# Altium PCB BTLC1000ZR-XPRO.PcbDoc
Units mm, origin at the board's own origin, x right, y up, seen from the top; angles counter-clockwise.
Board outline 66.5 x 30 mm, 4 copper layers (Top Layer LF-signals, GND, Mid-Layer 1, Bottom Layer LF-signals), stack 1.807 mm thick; 79 components, 62 nets, 283 pads, 205 vias.
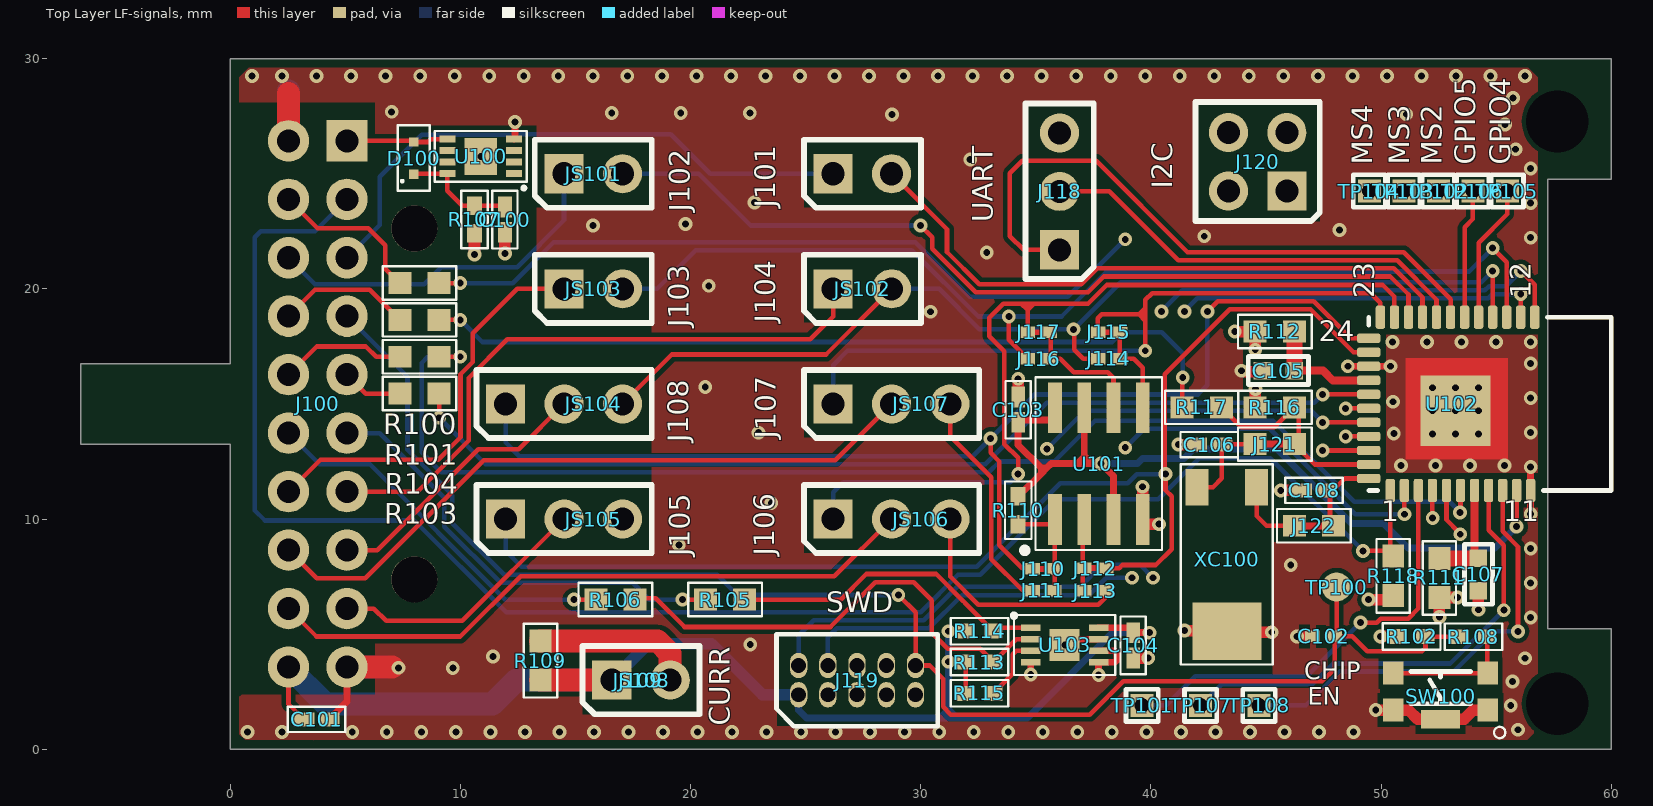
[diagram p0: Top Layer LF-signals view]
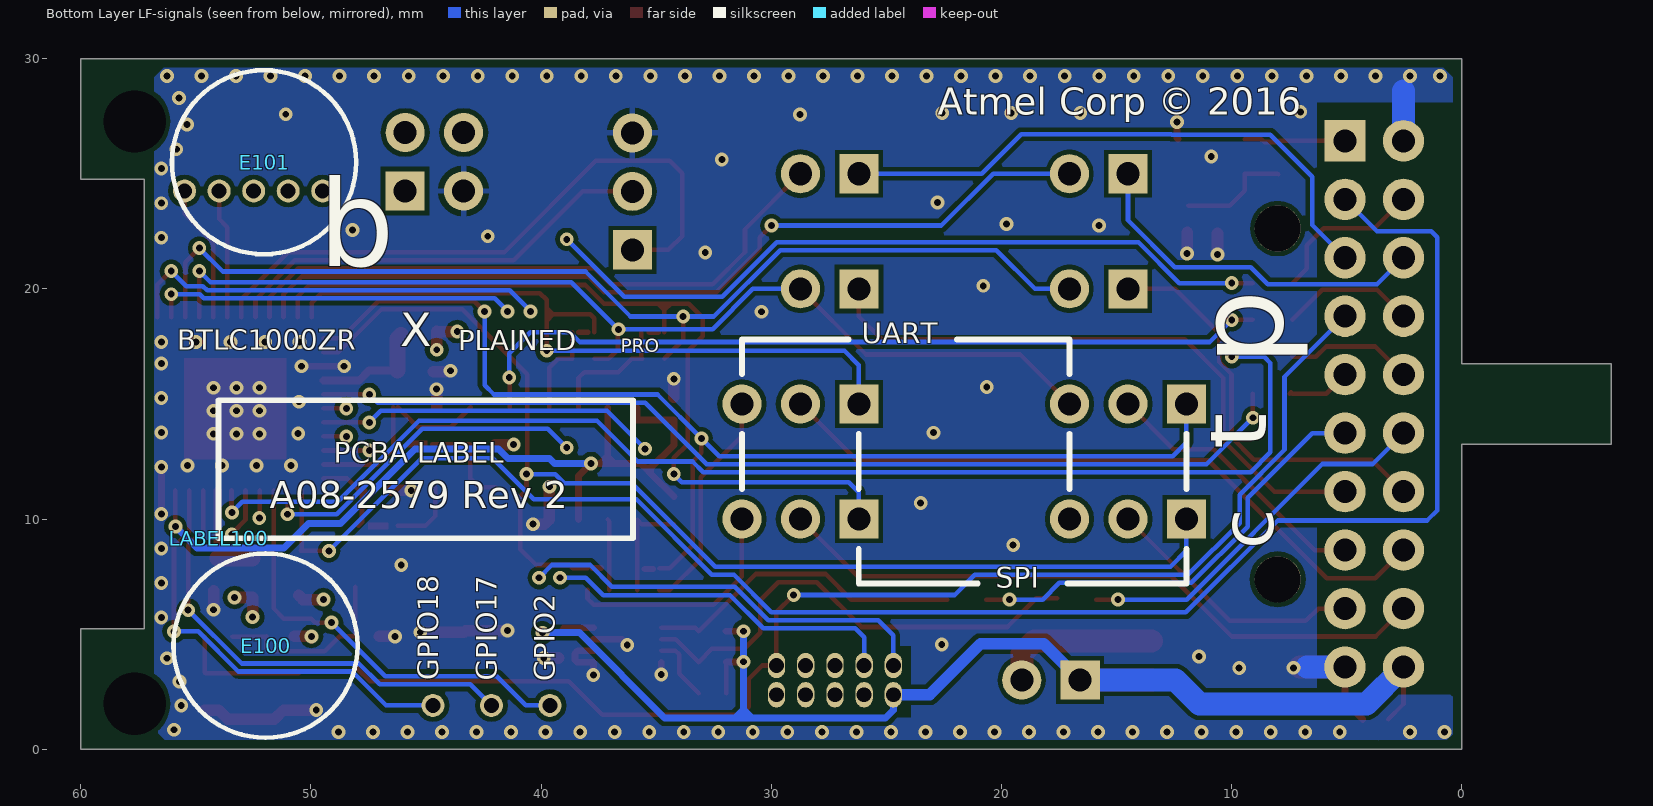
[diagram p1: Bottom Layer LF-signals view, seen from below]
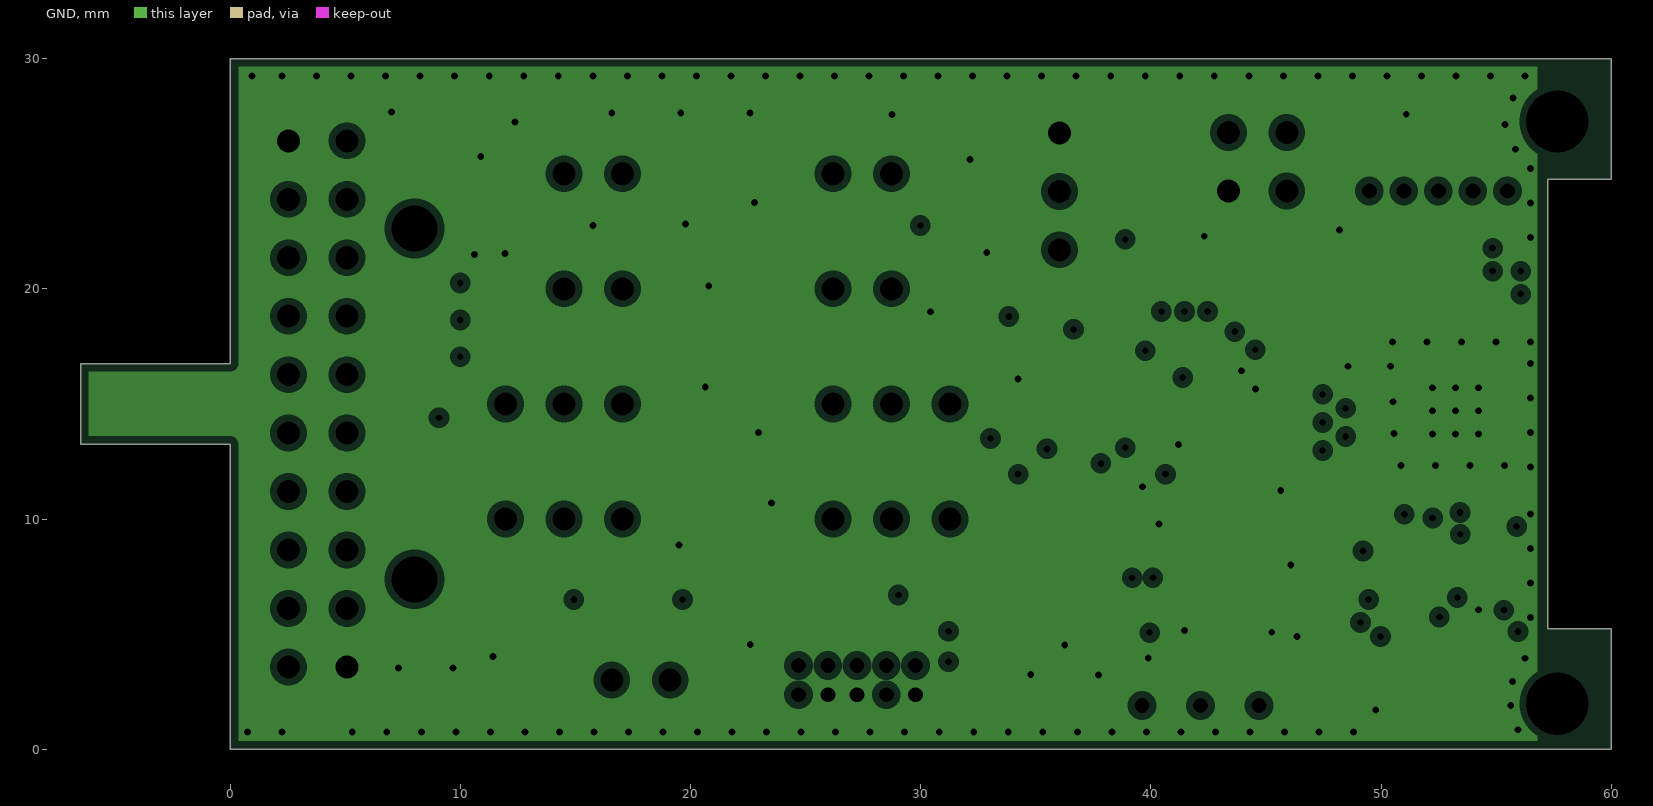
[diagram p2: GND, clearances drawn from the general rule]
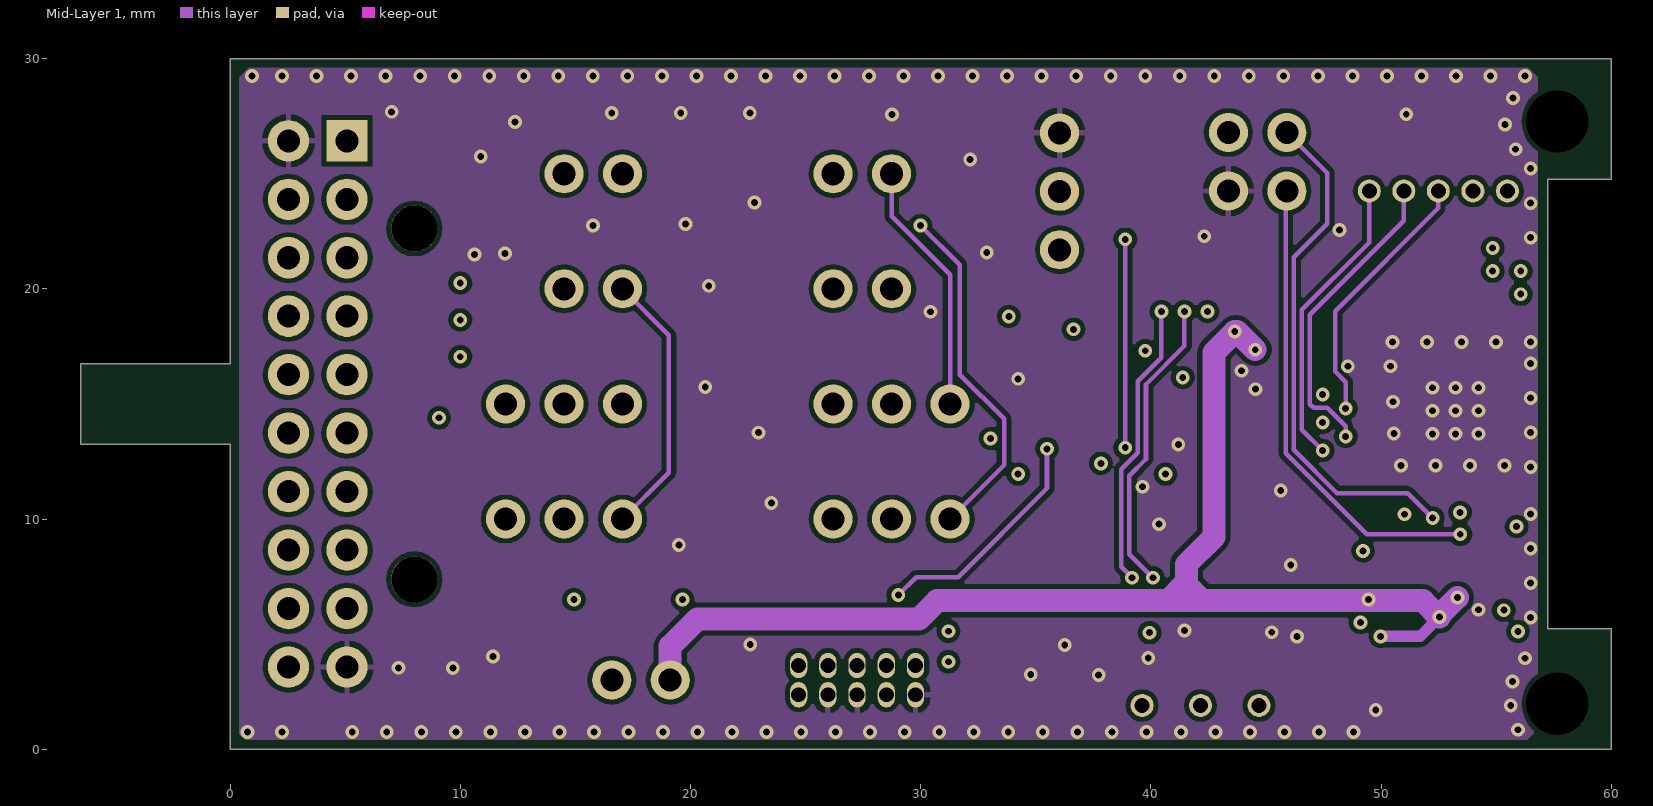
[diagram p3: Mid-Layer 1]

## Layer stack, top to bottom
Top Solder: solder mask 0.0102, Solder Resist, Dk 3.5
Top Layer LF-signals: signal copper 0.049
Dielectric1: core 0.118, FR-4, Dk 4.8
GND: plane copper 0.0356
Dielectric6: prepreg 1.2, FR-4, Dk 4.8
Mid-Layer 1: signal copper 0.0356
Dielectric2: core 0.32, FR-4, Dk 4.8
Bottom Layer LF-signals: signal copper 0.049
Bottom Solder: solder mask 0.0102, Solder Resist, Dk 3.5

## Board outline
-6.5,13.25 -6.5,16.75 0,16.75 0,30 60,30 60,24.769 57.229,24.769 57.229,5.24 60,5.24 60,0 0,0 0,13.25

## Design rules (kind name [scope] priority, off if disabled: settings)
AcuteAngle [All] p1: minimum=8.50000000000000E+0001 checktracksonly=FALSE
AssemblyTestPointUsage [All] p1: allowmultiple=TRUE
AssemblyTestpoint [(IsPad And OnMultiLayer)] p1: testpointundercomponent=TRUE minsize=0.55 maxsize=2 preferedsize=0.8 minholesize=0 maxholesize=1 preferedholesize=0.25 testpointgrid=0.025 usegrid=FALSE gridtolerance=0 allowsidebottom=TRUE minspacing=1.27 compbodyclearance=0.127
Clearance Clearance_POLY [InPolygon] p1: gap=0.203
Clearance [All] p2: gap=0.15
ComponentClearance [All] p1: gap=0.1 collisioncheckmode=3 verticalgap=0.1 showdistances=FALSE
DiffPairsRouting [All] p1: maxlimit=0.3 minlimit=0.15 mostfreqgap=0.2 toplayer_minwidth=0.381 toplayer_maxwidth=0.381 toplayer_prefwidth=0.381 midlayer1_minwidth=0.381 midlayer1_maxwidth=0.381 midlayer1_prefwidth=0.381 bottomlayer_minwidth=0.381 bottomlayer_maxwidth=0.381 bottomlayer_prefwidth=0.381 maxuncoupledlength=20
FabricationTestPointUsage TestPointUsage [All] p1: valid=0 allowmultiple=TRUE
FabricationTestpoint Testpoint [(IsPad And OnMultiLayer)] p1: side=2 testpointundercomponent=TRUE minsize=0.55 maxsize=2 preferedsize=0.8 minholesize=0 maxholesize=1 preferedholesize=0.25 testpointgrid=0 allowsidebottom=TRUE usegrid=FALSE gridtolerance=0 minspacing=1.27 compbodyclearance=0.127
HoleSize [All] p1: absolutevalues=TRUE maxlimit=10 minlimit=0.25 maxpercent=80.000 minpercent=20.000
HoleToHoleClearance [All] p1: gap=0.45 allowstackedmicrovias=TRUE
MinimumAnnularRing [All] p1: minimumring=0.15
MinimumSolderMaskSliver [All] p1: minsoldermaskwidth=0.1
PlaneClearance [All] p1: clearance=0.3
PlaneConnect PlaneConnect_1 [InComponent('U102')] p1: planeconnectstyle=Direct reliefexpansion=0.508 reliefentries=4 reliefconductorwidth=0.254 reliefairgap=0.254
PlaneConnect PlaneConnect_50mil [HasFootprint('AP8-00257')] p2: planeconnectstyle=Relief reliefexpansion=0.2 reliefentries=4 reliefconductorwidth=0.2 reliefairgap=0.2
PlaneConnect PlaneConnect_VIA [IsVia] p3: planeconnectstyle=Direct reliefexpansion=0.508 reliefentries=4 reliefconductorwidth=0.254 reliefairgap=0.254
PlaneConnect [All] p4: planeconnectstyle=Relief reliefexpansion=0.508 reliefentries=4 reliefconductorwidth=0.254 reliefairgap=0.254
PolygonConnect PolygonConnect_VIA [IsVia] p1: connectstyle=Direct reliefconductorwidth=0.254 reliefentries=4 polygonreliefangle="90 Angle" airgapwidth=0.254
PolygonConnect [All] p2: connectstyle=Relief reliefconductorwidth=0.254 reliefentries=4 polygonreliefangle="90 Angle" airgapwidth=0.254
RoutingVias [All] p1: holewidth=0.25 width=0.55 viastyle="Through Hole" minholewidth=0.25 minwidth=0.55 maxholewidth=0.5 maxwidth=1
SMDNeckDown [All] p1: percent=70.000
SilkToSilkClearance SilkToSilkClearance_Text [IsText vs IsText] p1: silktosilkclearance=0
SilkToSilkClearance [All] p2: silktosilkclearance=0.1
SilkToSolderMaskClearance SilkscreenOverComponentPads [IsPad] p1: minsilkscreentomaskgap=0.1 clearancetoexposedcopper=TRUE
SolderMaskExpansion SolderMaskTenting [IsVia AND NOT (IsFabTestpoint OR IsAssyTestpoint)] p1: expansion=-1
SolderMaskExpansion [All] p2: expansion=0.05
ViasUnderSMD [All] p1: allowed=FALSE
Width [All] p1: maxlimit=10 minlimit=0.2 preferedwidth=0.2
17 further rules are at their usual default settings.

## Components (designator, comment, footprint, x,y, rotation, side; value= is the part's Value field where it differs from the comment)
C100 "Recommended by Escatec. No datasheet available yet." AP1-00001 11.932,23.006 r270 top
C101 "Recommended by Escatec. No datasheet available yet." AP1-00001 3.749,1.293 r0 top
C102 "100n" AP1-00053 47.5,4.9 r180 top
C103 "CAP-NONPOL" AP1-00001 34.231,14.75 r90 top
C104 "CAP-NONPOL" AP1-00001 39.226,4.512 r270 top
C105 "Close to Pin22(VDDIO)of U101" AP1-00039 45.531,16.45 r180 top
C106 "CAP-NONPOL" AP1-00001 42.532,13.234 r180 top
C107 "Close to Pin22(VDDIO)of U101" AP1-00039 54.228,7.592 r270 top
C108 "CAP-NONPOL" AP1-00001 47.087,11.241 r180 top
D100 "Farnell# 1615809" AP4-00036 7.97,25.68 r90 top
E100 "" AP8-00192 51.967,4.5 r180 bottom
E101 "" AP8-00192 52.033,25.5 r180 bottom
J100 "" AP8-00621 3.8,15 r90 top locked
J101 "#NAME?" AP8-00733 27.462,25 r0 top
J102 "#NAME?" AP8-00733 15.771,25 r0 top locked
J103 "#NAME?" AP8-00733 15.771,20 r0 top locked
J104 "#NAME?" AP8-00733 27.462,20 r0 top
J105 "Same as A08-1614 but with 1mm hole for optimal reflow soldering (no misalignment of the component)" AP8-00745 14.501,10 r0 top
J106 "Same as A08-1614 but with 1mm hole for optimal reflow soldering (no misalignment of the component)" AP8-00745 28.732,10 r0 top
J107 "Same as A08-1614 but with 1mm hole for optimal reflow soldering (no misalignment of the component)" AP8-00745 28.732,15 r0 top locked
J108 "Same as A08-1614 but with 1mm hole for optimal reflow soldering (no misalignment of the component)" AP8-00745 14.501,15 r0 top locked
J109 "#NAME?" AP8-00733 17.844,3 r0 top locked
J110 "SMD-STRAP_CLOSED" AP8-00595 35.322,7.833 r180 top net-tie
J111 "SMD-STRAP_OPEN" AP8-00596 35.322,6.892 r180 top
J112 "SMD-STRAP_CLOSED" AP8-00595 37.57,7.868 r0 top net-tie
J113 "SMD-STRAP_OPEN" AP8-00596 37.57,6.892 r0 top
J114 "SMD-STRAP_OPEN" AP8-00596 38.169,16.962 r180 top
J115 "SMD-STRAP_CLOSED" AP8-00595 38.169,18.112 r180 top net-tie
J116 "SMD-STRAP_OPEN" AP8-00596 35.119,16.962 r180 top
J117 "SMD-STRAP_CLOSED" AP8-00595 35.119,18.112 r180 top net-tie
J118 "Same as A08-1614 but with 1mm hole for optimal reflow soldering (no misalignment of the component)" AP8-00745 36.032,24.235 r90 top
J119 "HEADER 2x5" AP8-00257 27.232,3 r0 top locked
J120 "HEADER 2x2" AP8-00179 44.632,25.52 r180 top
J121 "" AP9-00044 45.379,13.255 r180 top net-tie
J122 "" AP9-00044 47.077,9.706 r180 top net-tie
JS100 "To be used by request from ESCATEC" AP8-00525 25.937,32.276 r180 top
JS101 "To be used by request from ESCATEC" AP8-00525 15.771,25 r180 top
JS102 "To be used by request from ESCATEC" AP8-00525 27.462,20 r180 top
JS103 "To be used by request from ESCATEC" AP8-00525 15.771,20 r180 top
JS104 "To be used by request from ESCATEC" AP8-00525 15.771,15 r180 top
JS105 "To be used by request from ESCATEC" AP8-00525 15.771,10 r180 top
JS106 "To be used by request from ESCATEC" AP8-00525 30.002,10 r180 top
JS107 "To be used by request from ESCATEC" AP8-00525 30.002,15 r180 top
JS108 "To be used by request from ESCATEC" AP8-00525 17.844,3 r180 top
LABEL100 "" AP8-00317 54.005,9.161 r180 bottom
R100 "R2" AP2-00001 8.221,20.25 r0 top
R101 "R2" AP2-00001 8.221,18.65 r0 top
R102 "R2" AP2-00000 51.324,4.9 r0 top
R103 "R2" AP2-00001 8.221,15.45 r180 top
R104 "R2" AP2-00001 8.221,17.05 r0 top
R105 "R2" AP2-00001 21.501,6.5 r180 top
R106 "R2" AP2-00001 16.731,6.5 r0 top
R107 "" AP2-00000 10.61,23.013 r90 top
R108 "R2" AP2-00000 54.011,4.884 r0 top
R109 "R2" AP2-00001 13.474,3.85 r90 top
R110 "R2" AP2-00000 34.23,10.38 r90 top
R111 "R2" AP2-00001 52.528,7.44 r270 top
R112 "R2" AP2-00001 45.379,18.15 r180 top
R113 "R2" AP2-00000 32.55,3.784 r0 top
R114 "R2" AP2-00000 32.555,5.126 r180 top
R115 "R2" AP2-00000 32.55,2.427 r0 top
R116 "R2" AP2-00001 45.379,14.849 r0 top
R117 "R2" AP2-00001 42.206,14.849 r180 top
R118 "R2" AP2-00001 50.523,7.534 r90 top
SW100 "PUSHBUTTON2" AP8-00274 54.629,1.7 r180 top
TP100 "TESTPOINT" AP8-00010 48.064,7.046 r90 top
TP101 "TESTPOINT" AP8-00256 39.614,1.901 r90 top locked
TP102 "TESTPOINT" AP8-00256 52.483,24.25 r90 top
TP103 "TESTPOINT" AP8-00256 50.983,24.25 r90 top
TP104 "TESTPOINT" AP8-00256 49.483,24.25 r90 top
TP105 "TESTPOINT" AP8-00256 55.483,24.25 r90 top
TP106 "TESTPOINT" AP8-00256 53.983,24.25 r90 top
TP107 "TESTPOINT" AP8-00256 42.154,1.901 r90 top locked
TP108 "TESTPOINT" AP8-00256 44.694,1.901 r90 top locked
U100 "ATSHA204A-SWI" AP6-00409 10.88,25.753 r180 top
U101 "IS25LD020-JNLE" AP6-00000 35.832,9.977 r90 top
U102 "BTLC1000-ZR-XPRO" AP9-00156 54.73,15.004 r0 top
U103 "AT30TSx75x" AP6-00186 36.252,4.527 r0 top
XC100 "Farnell order no:1539364" AP7-00044 43.293,11.383 r180 top

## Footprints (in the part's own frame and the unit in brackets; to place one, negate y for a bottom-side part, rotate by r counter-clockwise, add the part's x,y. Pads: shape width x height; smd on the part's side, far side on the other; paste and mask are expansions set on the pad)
AP1-00001 [mm] "Standard 0402 SMD capacitor footprint"
  rect 0.9x0.6 smd: 1(-0.55,0) 2(0.55,0)
  silkscreen extent -1.25,-0.55 1.25,0.55, body extent -0.5,-0.3 0.5,0.3, height 0.2
AP1-00039 [mil] "Capacitor 0603 Hight 0.8mm"
  rect 30x30 smd: 1(-27.5,0) 2(27.5,0)
  silkscreen extent -52,-24 51,24, body extent -31,-16 32,16, height 12
AP1-00053 [mm] "Chip Capacitor, 2-Leads, Body 1.0x0.5mm, IPC High Density"
  rect 0.65x0.5 smd: 1(-0.475,0) 2(0.475,0)
  body extent -0.5,-0.3 0.5,0.3, height 0.2
AP2-00000 [mm] "Standard 0402 SMD resistor footprint"
  rect 0.8x0.65 smd: 1(-0.6,0) 2(0.6,0)
  silkscreen extent -1.25,-0.58 1.25,0.58, body extent -0.5,-0.3 0.5,0.3, height 0.2
AP2-00001 [mm]
  rect 1x0.95 smd: 1(-0.85,0) 2(0.85,0)
  silkscreen extent -1.6,-0.72 1.6,0.72, body extent -0.8,-0.4 0.8,0.4, height 0.3
AP4-00036 [mm] "Molded Diode, 2-Leads, Body 1,2x0,8mm, IPC Medium Density"
  rect 0.4x0.4 smd: 1(-0.7,0) 2(0.7,0)
  silkscreen extent -1.43,-0.7 1.43,0.7, body extent -0.8,-0.4 0.8,0.4, height 0.7
AP6-00000 [mm]
  rect 2.2x0.6 smd: 1(0,0) 2(0,-1.27) 3(0,-2.54) 4(0,-3.81) 5(4.85,-3.81) 6(4.85,-2.54) 7(4.85,-1.27) 8(4.85,0)
  silkscreen extent -1.46,-4.65 6.17,1.44, body extent -0.67,-4.4 5.52,0.6, height 1.7
AP6-00186 [mm] "8M2, 8-lead 2.0x3.0 mm Body, 0.50 mm Pitch,  WDFN, Very Very Thin, Dual No Lead Package"
  round 0.264 on Top Paste: 0(-0.425,-0.4) 0(-0.425,0.4) 0(0,0) 0(0.425,-0.4) 0(0.425,0.4)
  rect 0.85x0.3 smd: 1(-1.475,0.75) 2(-1.475,0.25) 3(-1.475,-0.25) 4(-1.475,-0.75) 5(1.475,-0.75) 6(1.475,-0.25) 7(1.475,0.25) 8(1.475,0.75)
  rect 1.3x1.4 smd paste-0.7: 9(0,0)
  silkscreen extent -2.26,-1.3 2.2,1.33, body extent -1.53,-1 1.53,1, height 0.76
AP6-00409 [mm]
  rect 0.7x0.3 smd mask+0.075: 1(-1.45,0.75) 2(-1.45,0.25) 3(-1.45,-0.25) 4(-1.45,-0.75) 5(1.45,-0.75) 6(1.45,-0.25) 7(1.45,0.25) 8(1.45,0.75)
  rect 1.4x1.6 smd paste-0.025 mask+0.075: 9(0,0)
  silkscreen extent -2,-1.1 2,1.45, body extent -1.55,-1.05 1.55,1.05, height 0.6
AP7-00044 [mm]
  rect 1x1.6 smd: 1(-1.3,0) 2(1.3,0)
  rect 3x2.5 smd: 3(0,6.25)
  silkscreen extent -2,-1 2,7.7, body extent -1.5,-0.7 1.5,7.4, height 2.08
AP8-00010 [mm] "Testpad 50mil"
  round 1.27 smd paste-0.635: 1(0,0)
AP8-00179 [mm]
  rect 1.75x1.75 on Top Paste: 0(-1.27,1.27) 1(1.27,1.27) 2(1.27,-1.27) 3(-1.27,-1.27)
  rect 1.7x1.7 / inner round 1.7 / far side rect 1.7x1.7 hole 1: 1(-1.27,1.27)
  round 1.7 hole 1: 2(1.27,1.27) 3(-1.27,-1.27) 4(1.27,-1.27)
  silkscreen extent -2.7,-2.6 2.7,2.58, body extent -2.54,-2.54 2.54,2.54, height 9.42
AP8-00192 [mm]
  silkscreen extent -4,-4 4,4, body extent -4,-4 4,4, height 2.79
AP8-00256 [mm]
  rect 1x1 / inner round 1 / far side round 1 hole 0.65: 1(0,0)
  silkscreen extent -0.7,-0.7 0.7,0.7, body extent -0.5,-0.5 0.5,0.5, height 1.1
AP8-00257 [mm]
  oval 0.75x1.1 hole 0.65: 1(-2.54,-0.635) 2(-2.54,0.635) 3(-1.27,-0.635) 4(-1.27,0.635) 5(0,-0.635) 6(0,0.635) 7(1.27,-0.635) 8(1.27,0.635) 9(2.54,-0.635) 10(2.54,0.635)
  oval 0.75x1.1 on Top Paste: 1(-2.54,-0.635) 2(-2.54,0.635) 3(-1.27,-0.635) 4(-1.27,0.635) 5(0,-0.635) 6(0,0.635) 7(1.27,-0.635) 8(1.27,0.635) 9(2.54,-0.635) 10(2.54,0.635)
  silkscreen extent -3.5,-2 3.5,2, body extent -3.15,-1.64 3.2,1.79, height 3.88
AP8-00274 [mm] "SMD 4.6X2.8 push button. KMR221G"
  rect 0.9x1 smd: 1(0,0) 2(0,-1.6) 3(4.1,0) 4(4.1,-1.6)
  rect 1.7x0.8 smd: 5(2.05,0.4)
  silkscreen extent -0.77,-1.68 3.35,1.22, body extent -0.25,-2.2 4.35,0.6, height 1.9
AP8-00317 [mm] "Placement area for 18x6mm sticker"
  silkscreen extent 0,0 18,6
AP8-00525 [mm] "Jumper 2.54mm, 3D"
  body extent -4.02,6.06 0.96,8.5, height 8.77
AP8-00595 [mm]
  rect 0.65x0.5 smd paste-1: 1(-0.475,0) 2(0.475,0)
  Top Layer LF-signals lines w0.254: 0.2,0 -0.175,0
AP8-00596 [mm]
  rect 0.65x0.5 smd paste-1: 1(-0.475,0) 2(0.475,0)
AP8-00621 [mm] "2x5 Receptacle THM, Right Angle. No Guide. 2.54mm pitch. Length 13.2mm, width 5.0mm, height 5mm"
  rect 1.8x1.8 hole 1: 1(11.43,-1.27)
  rect 2.1x2.1 on Top Paste: 1(11.43,-1.27) 2(11.43,1.27) 3(8.89,-1.27) 4(8.89,1.27) 5(6.35,-1.27) 6(6.35,1.27) 7(3.81,-1.27) 8(3.81,1.27) 9(1.27,-1.27) 10(1.27,1.27) 11(-1.27,-1.27) 12(-1.27,1.27) 13(-3.81,-1.27) 14(-3.81,1.27) 15(-6.35,-1.27) 16(-6.35,1.27) 17(-8.89,-1.27) 18(-8.89,1.27) 19(-11.43,-1.27) 20(-11.43,1.27)
  round 1.8 hole 1: 2(11.43,1.27) 3(8.89,-1.27) 4(8.89,1.27) 5(6.35,-1.27) 6(6.35,1.27) 7(3.81,-1.27) 8(3.81,1.27) 9(1.27,-1.27) 10(1.27,1.27) 11(-1.27,-1.27) 12(-1.27,1.27) 13(-3.81,-1.27) 14(-3.81,1.27) 15(-6.35,-1.27) 16(-6.35,1.27) 17(-8.89,-1.27) 18(-8.89,1.27) 19(-11.43,-1.27) 20(-11.43,1.27)
  body extent -12.95,-1.47 12.95,11.3, height 4.98
AP8-00733 [mm] "Pin header 1x2 Pin in Paste"
  rect 1.7x1.7 / inner round 1.7 / far side rect 1.7x1.7 hole 1: 1(-1.27,0)
  rect 2.1x2.1 on Top Paste: 1(-1.27,0) 2(1.27,0)
  round 1.7 hole 1: 2(1.27,0)
  silkscreen extent -2.54,-1.48 2.54,1.48, body extent -2.54,-1.27 2.54,1.27, height 8.38
AP8-00745 [mm] "THM Pin-header 1x3 100mil pitch, 1mm hole"
  rect 1.7x1.7 / inner round 1.7 / far side rect 1.7x1.7 hole 1: 1(-2.54,0)
  rect 2.1x2.1 on Top Paste: 1(-2.54,0) 2(0,0) 3(2.54,0)
  round 1.7 hole 1: 2(0,0) 3(2.54,0)
  silkscreen extent -3.81,-1.48 3.81,1.48, body extent -3.81,-1.27 3.81,1.27, height 8.38
AP9-00044 [mm]
  rect 1x0.95 smd paste-1: 1(-0.85,0) 2(0.85,0)
  Top Layer LF-signals region: -0.45,-0.15 0.45,-0.15 0.45,0.15 -0.45,0.15
  silkscreen extent -1.6,-0.72 1.6,0.72, body extent -0.8,-0.4 0.8,0.4, height 0.3
AP9-00156 [mil] "ATSAMB11-ZR110CA"
  rrect50% 16x40 smd: 1(-170.5,-148.2) 2(-146.5,-148.2) 3(-122.5,-148.2) 4(-98.5,-148.2) 5(-74.5,-148.2) 6(-50.5,-148.2) 7(-26.5,-148.2) 8(-2.5,-148.2) 9(21.5,-148.2) 10(45.5,-148.2) 11(69.5,-148.2) 12(76.5,148.2) 13(52.5,148.2) 14(28.5,148.2) 15(4.5,148.2) 16(-19.5,148.2) 17(-43.5,148.2) 18(-67.5,148.2) 19(-91.5,148.2) 20(-115.5,148.2) 21(-139.5,148.2) 22(-163.5,148.2) 23(-187.5,148.2)
  rrect50% 40x16 smd: 24(-207.5,112.2) 25(-207.5,88.2) 26(-207.5,64.2) 27(-207.5,40.2) 28(-207.5,16.2) 29(-207.5,-7.8) 30(-207.5,-31.8) 31(-207.5,-55.8) 32(-207.5,-79.8) 33(-207.5,-103.8) 34(-207.5,-127.8)
  rect 120x120 smd: 35(-59,-11.9)
  silkscreen extent -208,-148 207,148, body extent -207,-148 208,148, height 32

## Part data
C100 C101: library part A01-0347, "Ceramic capacitor, SMD 0402, X5R, 6.3V, +/-20% (de33687)"
C102 C103 C104: library part A01-0246, "Ceramic capacitor, SMD 0402, X7R, 16V, +/-10%"
C105 C107: library part A01-0491, "Ceramic capacitor, SMD 0603, X5R, 16V, 10UF ± 20% (High Density)"
C106 C108: library part A01-0013, "Ceramic capacitor, SMD 0402, NP0, 50V, +/-5%"
D100: library part A04-0049, "Schottky diode, If:200mA, Vf:0.35V, Vrrm:30V, SOD-523"
E100 E101: library part A08-0053, "2.8mm adhesive feet,diam 8.0mm"
J100: library part A08-1512, "2x10, female pin header receptable, right-angled, 2.54mm pitch, THM, Pin In Paste"
J101 J102 J103 J104 J109: library part A08-1754, "1x2 pin header, 2.54mm pitch, Pin-in-Paste THM"
J105 J106 J107 J108 J118: library part A08-1799, "1x3 pin header, 2.54mm pitch, Pin-in-Paste THM, 1mm hole"
J110 J112 J115 J117: library part A08-1454, "Closed Link 0402"
J111 J113 J114 J116: library part A08-1455, "Open Link 0402"
J119: library part A08-0385, "2x5 pin header, 1.27mm pitch, THM"
J120: library part A08-0115, "2x2 pin header, 2.54 mm pitch, Pin-in-Paste THM"
J121 J122: library part A09-0783, "Default closed SMD strap, 0603 size"
JS100 JS101 JS102 JS103 JS104 JS105 JS106 JS107 JS108: library part A08-0543, "Jumper cap for 2.54mm pinheader"
LABEL100: library part A09-0611, "PCBA identification label PP Top White Gloss"
R100 R101 R103 R104 R105 R106 R109 R111 R112: library part A02-0001, "Thick film resistor, SMD 0603, 1/10W, 1%"
R102 R107 R110 R115: library part A02-0260, "Thick film resistor, SMD 0402, 1/16W, 1%"
R108: library part A02-0178, "Thick film resistor, SMD 0402, 1/16W, 1%"
R113 R114: library part A02-0228, "Thick film resistor, SMD 0402, 1/16W, 1%"
R116: library part A02-0118, "Thick film resistor, SMD 0603, 1/10W, 1%"
R117: library part A02-0124, "Thick film resistor, SMD 0603, 1/10W, 1%"
R118: library part A02-0122, "Thick film resistor, SMD 0603, 1/10W, 1%"
SW100: library part A08-0420, "Microminiature Tact Switch for SMT"
TP100: library part A08-0004, "Single SMD testpad"
TP101 TP102 TP103 TP104 TP105 TP106 TP107 TP108: library part A09-0290, "Hole for user grid with 1.27 mm pitch, 1x1 mm pad"
U100: library part A06-1276, "ATSHA204 with 1-wire interface and UDFN8 package"
U101: library part A06-1302, "2 Mbit SPI Serial Flash upto 80MHz"
U102: library part A06-1404, "Bluetooth module, 34pin WITH chip Antenna"
U103: library part A06-1300, "SINGLE DIGITAL TEMPERATURE SENSOR W/ SERIAL EEPROM, UDFN8"
XC100: library part A07-0052, "32k768 crystal, +-20ppm, CL=7pF, max ESR 60kOhm, SMD"

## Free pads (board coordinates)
  round 0 hole 2.7 unplated paste-2.6: 0(57.65,27.275) 1(57.65,1.975)
  round 2 hole 2 unplated: 2(8,22.62) 3(8,7.38)

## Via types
v1: diameter 0.6, hole 0.3, Top Layer LF-signals to Bottom Layer LF-signals, 205 vias

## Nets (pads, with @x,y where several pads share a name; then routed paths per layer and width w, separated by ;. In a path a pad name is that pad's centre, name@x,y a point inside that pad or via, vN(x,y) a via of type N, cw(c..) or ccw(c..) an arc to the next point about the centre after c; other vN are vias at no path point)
AO_GPIO_1: R100.2 U102.2 | length 56.7
  Top Layer LF-signals w0.2: R100.2 v1(9.992,20.25) ; v1(51.008,10.206) U102.2
  Mid-Layer 1 w0.2: v1(38.881,13.1) 38.881,22.148 v1(38.883,22.15)
  Bottom Layer LF-signals w0.2: v1(9.992,20.25) 12.265,20.25 14.042,22.027 29.756,22.027 32.126,19.657 36.391,19.657 v1(38.883,22.15) ; v1(38.881,13.1) 39.707,13.926 45.157,13.926 48.877,10.206 v1(51.008,10.206)
AO_GPIO_2: TP101.1 U102.3 | length 18.9
  Top Layer LF-signals w0.2: v1(49.1,5.5) 49.807,5.5 49.98,5.673 51.179,5.673 51.618,6.113 U102.3
  Bottom Layer LF-signals w0.2: TP101.1 40.656,1.901 41.928,3.173 46.773,3.173 v1(49.1,5.5)
CHIP_EN: C102.1 J100.7@5.07,18.81 J119.10@29.772,3.635 R102.2 R108.1 TP100.1 U102.30 | length 90.2
  Top Layer LF-signals w0.2: v1(29.024,6.7) 29.772,5.952 29.772,3.635 30.384,3.635 30.971,3.049 30.971,1.84 31.308,1.503 37.345,1.503 38.794,2.952 47.431,2.952 47.975,3.495 C102.1 ; v1@47.611,14.197 U102.30 ; TP100.1 48.064,4.989 C102.1 ; R102.2 R102.2@51.924,4.884 ; R108.1 R102.2@51.924,4.884 ; C102.1 48.736,4.9 49.389,4.248 51.776,4.248 51.924,4.396 R102.2@51.924,4.884
  Mid-Layer 1 w0.2: v1(29.024,6.7) 29.799,7.475 31.623,7.475 35.481,11.334 v1(35.481,13.05)
  Bottom Layer LF-signals w0.2: J100.7@5.07,18.81 7.701,16.179 7.701,13.011 9.65,11.061 9.65,9.822 11.897,7.575 21.151,7.575 22.026,6.7 v1(29.024,6.7) ; v1(35.481,13.05) 37.131,14.7 46.956,14.7 v1(47.459,14.197)
DEBUG_I2C_SCL: J120.1@45.902,24.25 U102.5 | length 22.5
  Top Layer LF-signals w0.2: U102.5 52.837,9.96 v1@53.357,9.44
  Mid-Layer 1 w0.2: J120.1@45.902,24.25 45.854,24.203 45.854,12.859 49.374,9.34 v1(53.437,9.34)
DEBUG_I2C_SDA: J120.3@45.902,26.79 U102.4 | length 23.6
  Top Layer LF-signals w0.2: U102.4 52.228,10.05 v1(52.237,10.04)
  Mid-Layer 1 w0.2: J120.3@45.902,26.79 47.659,25.033 47.659,22.832 46.204,21.378 46.204,13.004 48.082,11.127 51.151,11.127 v1(52.237,10.04)
DEBUG_UART_RXD: J118.1@36.032,21.695 U102.18 | length 27.8
  Top Layer LF-signals w0.2: J118.1@36.032,21.695 34.464,21.695 33.867,22.292 33.867,25.016 34.409,25.558 37.618,25.558 41.588,21.588 50.982,21.588 53.015,19.555 U102.18
DEBUG_UART_TXD: J118.2@36.032,24.235 U102.19 | length 19.1
  Top Layer LF-signals w0.2: J118.2@36.032,24.235 38.19,24.235 41.187,21.238 50.69,21.238 52.405,19.522 U102.19
EXT_CLK_RTC: R101.2 R117.2 | length 35.6
  Top Layer LF-signals w0.2: R101.2 v1(9.992,18.65) ; R117.2 41.356,16.124 v1(41.381,16.15)
  Bottom Layer LF-signals w0.2: v1(9.992,18.65) 10.952,17.69 38.311,17.69 38.742,18.121 40.462,18.121 41.381,17.201 v1(41.381,16.15)
FLASH_SPI_MISO: J112.1 J113.1 U101.2 | length 3.1
  Top Layer LF-signals w0.2: J113.1@37.031,6.916 37.031,7.862 37.031,9.907 U101.2
FLASH_SPI_MOSI: J114.1 J115.1 U101.5 | length 4.1
  Top Layer LF-signals w0.2: J115.1 J114.1 39.258,16.962 39.642,16.579 U101.5
FLASH_SPI_SCK: J116.1 J117.1 U101.6 | length 5.6
  Top Layer LF-signals w0.2: J117.1@35.644,18.112 35.644,17.012 J116.1 36.059,16.962 36.646,16.376 38.127,16.376 38.372,16.131 U101.6
FLASH_SPI_SS: J110.1 J111.1 R110.1 U101.1 | length 4.7
  Top Layer LF-signals w0.2: R110.1 35.634,9.78 35.819,9.965 35.819,7.862 J111.1@35.819,6.917
GND: C100.2 C101.2 C102.2 C103.2 C104.2 C105.2 C106.2 C107.2 C108.2 J100.2@2.53,26.43 J100.19@5.07,3.57 J118.3@36.032,26.775 J119.3@25.962,2.365 J119.5@27.232,2.365 J119.9@29.772,2.365 J120.2@43.362,24.25 R107.1 R116.1 SW100.1 SW100.3 SW100.5 U100.4 U100.9 U101.4 U102.11 U102.26 U102.35 U103.4 U103.5 U103.6 U103.7 U103.9 XC100.3 | length 39
  Top Layer LF-signals w0.3: C101.2 5.07,2.064 J100.19@5.07,3.57 ; U100.4 12.374,26.546 v1(12.374,27.25) ; v1(34.777,3.24) U103.4 ; v1(36.252,4.527) 36.502,4.777 U103.7 ; v1(37.727,3.228) U103.5 38.423,3.777 38.518,3.873 38.518,4.164 38.404,4.277 U103.6 ; v1(48.552,16.635) v1(50.405,16.635) ; v1(56.495,10.221) v1(56.495,12.259)
  Top Layer LF-signals w0.5: v1(10.61,21.496) R107.1 ; v1(11.932,21.539) C100.2 ; C103.2 v1(34.231,16.09) ; C104.2 v1(39.879,3.962) ; v1(39.631,11.4) 39.642,11.389 U101.4 39.855,9.764 39.867,9.776 v1(40.351,9.776) ; v1(41.188,13.234) C106.2 ; v1(41.451,5.15) XC100.3@43.276,5.15 ; XC100.3 43.346,5.08 v1(45.247,5.08) ; v1(43.937,16.44) 43.973,16.405 C105.2@44.681,16.405 ; R116.1 44.529,15.632 v1(44.537,15.64) ; v1(45.639,11.241) C108.2 ; v1(46.337,4.9) C102.2 ; v1(49.766,1.7) SW100.3 51.186,1.7 51.586,1.3 SW100.5 53.602,1.3 54.002,1.7 SW100.1 ; v1(54.228,6.058) C107.2
  Top Layer LF-signals w1: J100.2@2.53,26.43 2.53,28.477 ; J100.19@5.07,3.57 v1@7.032,3.57
  Mid-Layer 1 w0.5: v1(34.231,16.09) v1@34.231,16.124 ; v1(39.631,11.4) v1@39.637,11.406
  Bottom Layer LF-signals w1: J100.2@2.53,26.43 2.53,28.588 ; J100.19@5.07,3.57 6.727,3.57
  other v1: 0.75,0.75 2.25,0.75 5.299,0.75 6.799,0.75 8.299,0.75 9.799,0.75 11.299,0.75 12.799,0.75 14.299,0.75 15.799,0.75 17.299,0.75 18.799,0.75 20.299,0.75 21.799,0.75 23.299,0.75 24.799,0.75 26.299,0.75 27.799,0.75 29.299,0.75 30.799,0.75 32.299,0.75 33.799,0.75 35.299,0.75 36.799,0.75 38.299,0.75 39.799,0.75 41.299,0.75 42.799,0.75 44.299,0.75 45.799,0.75 47.299,0.75 48.799,0.75 55.94,0.844 55.632,1.904 55.709,2.939 7.311,3.536 9.668,3.524 56.25,3.95 11.42,4.032 22.591,4.544 56.495,5.721 56.495,7.221 46.072,7.998 56.495,8.721 19.488,8.872 23.506,10.7 50.857,12.323 52.357,12.323 53.857,12.323 55.357,12.323 50.549,13.712 52.23,13.701 53.231,13.701 54.232,13.701 22.947,13.751 56.495,13.759 52.23,14.702 53.231,14.702 54.232,14.702 50.517,15.094 56.495,15.259 52.23,15.703 53.231,15.703 54.232,15.703 20.636,15.73 56.495,16.759 50.495,17.685 51.995,17.685 53.495,17.685 54.995,17.685 56.495,17.685 30.424,19.006 20.785,20.131 32.866,21.576 56.495,22.221 42.312,22.286 48.187,22.56 15.753,22.752 19.783,22.817 56.495,23.721 22.77,23.757 56.495,25.221 32.145,25.618 10.88,25.753 55.843,26.066 55.376,27.143 28.744,27.573 51.089,27.586 16.572,27.645 19.572,27.645 22.572,27.645 7.013,27.691 55.727,28.297 0.938,29.25 2.25,29.25 3.75,29.25 5.25,29.25 6.75,29.25 8.25,29.25 9.75,29.25 11.25,29.25 12.75,29.25 14.25,29.25 15.75,29.25 17.25,29.25 18.75,29.25 20.25,29.25 21.75,29.25 23.25,29.25 24.75,29.25 26.25,29.25 27.75,29.25 29.25,29.25 30.75,29.25 32.25,29.25 33.75,29.25 35.25,29.25 36.75,29.25 38.25,29.25 39.75,29.25 41.25,29.25 42.75,29.25 44.25,29.25 45.75,29.25 47.25,29.25 48.75,29.25 50.25,29.25 51.75,29.25 53.25,29.25 54.75,29.25 56.25,29.25
GPIO_MS1: R103.1 U102.28 | length 43.5
  Top Layer LF-signals w0.2: v1(9.071,14.401) R103.1 ; v1@47.525,15.416 U102.28
  Bottom Layer LF-signals w0.2: v1(9.071,14.401) 11.089,12.383 32.808,12.383 35.476,15.05 47.093,15.05 v1(47.459,15.416) ; v1@47.492,15.383 v1@47.525,15.416
GPIO_MS2: TP102.1 U102.29 | length 12.5
  Top Layer LF-signals w0.2: v1@48.491,14.806 U102.29
  Mid-Layer 1 w0.2: v1(48.459,14.806) 48.459,15.95 48.002,16.407 48.002,19.029 52.483,23.511 TP102.1
GPIO_MS3: TP103.1 U102.31 | length 14.3
  Top Layer LF-signals w0.2: v1@48.471,13.587 U102.31
  Mid-Layer 1 w0.2: v1(48.459,13.587) 48.459,14.028 47.657,14.83 47.069,14.83 46.904,14.994 46.904,18.875 50.983,22.954 TP103.1
GPIO_MS4: TP104.1 U102.32 | length 14.7
  Top Layer LF-signals w0.2: v1@47.639,12.977 U102.32
  Mid-Layer 1 w0.2: v1(47.459,12.977) 46.554,13.882 46.554,19.085 49.483,22.014 TP104.1
I2C_SCL: R106.2 R113.2 U103.2 | length 21.2
  Top Layer LF-signals w0.2: R106.2@17.581,6.554 18.489,6.554 19.732,5.311 26.078,5.311 28.027,7.26 29.694,7.26 30.476,6.478 30.476,5.057 31.174,4.359 32.575,4.359 R113.2 34.143,4.777 U103.2
I2C_SDA: R105.1 R114.1 U103.1 | length 15.6
  Top Layer LF-signals w0.2: R105.1 26.524,6.5 27.634,7.61 30.671,7.61 ; 31.845,6.436 30.671,7.61 ; U103.1 33.307,5.277 R114.1 30.671,7.61
LP_GPIO_4: TP105.1 U102.16 | length 6
  Top Layer LF-signals w0.2: U102.16 54.234,22.003 55.483,23.253 TP105.1
LP_GPIO_5: TP106.1 U102.17 | length 5.6
  Top Layer LF-signals w0.2: U102.17 53.625,22.674 53.983,23.033 TP106.1
LP_GPIO_16: R104.2 U102.6 | length 55.6
  Top Layer LF-signals w0.2: R104.2 v1(9.992,17.05) ; v1@53.447,10.285 U102.6
  Bottom Layer LF-signals w0.2: v1(9.992,17.05) 8.584,17.05 8.313,16.778 8.313,12.894 9.174,12.033 32.953,12.033 33.421,12.5 35.253,12.5 35.79,12.5 37.566,14.276 45.302,14.276 48.822,10.756 52.976,10.756 v1@53.447,10.285
  other v1: 53.429,10.285
LP_GPIO_17: TP107.1 U102.8 | length 20.4
  Top Layer LF-signals w0.2: U102.8 54.666,9.517 55.328,8.855 v1(55.328,6.04)
  Bottom Layer LF-signals w0.2: TP107.1 43.076,2.823 47.01,2.823 47.912,3.725 53.01,3.725 55.325,6.04 v1(55.328,6.04)
LP_GPIO_18: TP108.1 U102.9 | length 20.8
  Top Layer LF-signals w0.2: v1(55.945,5.116) 55.945,8.799 55.276,9.468 ; 55.276,9.468 U102.9 55.276,9.468
  Bottom Layer LF-signals w0.2: TP108.1 46.735,1.901 48.209,3.375 53.155,3.375 54.896,5.116 v1(55.945,5.116)
NetC100_1: C100.1 D100.1 R107.2 U100.8 | length 4.9
  Top Layer LF-signals w0.2: D100.1 7.993,25.003 U100.8 9.43,24.26 10.077,23.613 R107.2 C100.1@11.875,23.613
NetC106_1: C106.1 J121.2 XC100.2 | length 4.4
  Top Layer LF-signals w0.2: XC100.2 42.692,11.383 43.082,11.773 C106.1 43.103,13.255 J121.2@44.729,13.255
NetD100_2: D100.2 J100.1@5.07,26.43 U100.5 | length 4.4
  Top Layer LF-signals w0.2: J100.1@5.07,26.43 7.92,26.43 D100.2 8.581,26.38 8.704,26.503 U100.5
NetJ100_4: J100.4@2.53,23.89 R100.1 | length 6.9
  Top Layer LF-signals w0.2: J100.4@2.53,23.89 3.79,22.63 5.991,22.63 6.733,21.888 6.733,20.87 R100.1@7.353,20.25
NetJ100_5: J100.5@5.07,21.35 J101.1@26.192,25 | length 25.4
  Bottom Layer LF-signals w0.2: J100.5@5.07,21.458 5.07,21.35 6.492,22.772 6.492,24.876 8.316,26.7 12.602,26.7 12.618,26.717 19.139,26.717 20.856,25 J101.1@26.192,25
NetJ100_6: J100.6@2.53,21.35 J102.1@14.501,25 | length 15.6
  Bottom Layer LF-signals w0.2: J100.6@2.53,21.35 3.68,20.2 8.421,20.2 9.167,20.946 12.464,20.946 14.501,22.983 J102.1@14.501,25
NetJ100_8: J100.8@2.53,18.81 R101.1 | length 5.9
  Top Layer LF-signals w0.2: J100.8@2.53,18.81 3.68,19.96 6.061,19.96 R101.1
NetJ100_9: J100.9@5.07,16.27 R103.2 | length 2.7
  Top Layer LF-signals w0.2: J100.9@5.07,16.27 5.89,15.45 R103.2 ; R103.2@7.417,15.496 R103.2@7.463,15.45
NetJ100_10: J100.10@2.53,16.27 R104.1 | length 5.5
  Top Layer LF-signals w0.2: J100.10@2.53,16.27 3.756,17.496 5.894,17.496 6.34,17.05 R104.1
NetJ100_11: J100.11@5.07,13.73 R105.2 | length 19.3
  Top Layer LF-signals w0.2: v1(19.651,6.5) R105.2
  Bottom Layer LF-signals w0.2: J100.11@5.07,13.73 6.487,13.73 9.3,10.916 9.3,9.669 11.744,7.225 17.478,7.225 18.203,6.5 v1(19.651,6.5)
NetJ100_12: J100.12@2.53,13.73 R106.1 | length 16.3
  Top Layer LF-signals w0.2: v1(14.927,6.5) R106.1
  Bottom Layer LF-signals w0.2: J100.12@2.53,13.73 3.87,12.39 6.064,12.39 11.954,6.5 v1(14.927,6.5)
NetJ100_13: J100.13@5.07,11.19 J104.1@26.192,20 | length 27.1
  Top Layer LF-signals w0.2: J100.13@5.07,11.19 8.134,11.19 10.353,13.409 10.353,16.127 12.034,17.807 25.202,17.807 26.192,18.797 J104.1@26.192,20
NetJ100_14: J100.14@2.53,11.19 J103.1@14.501,20 | length 18
  Top Layer LF-signals w0.2: J100.14@2.53,11.19 3.92,12.58 9.029,12.58 10.003,13.554 10.003,16.284 10.542,16.822 10.542,16.885 10.542,18.074 12.468,20 J103.1@14.501,20
NetJ100_15: J100.15@5.07,8.65 J108.2@14.501,15 | length 12.1
  Top Layer LF-signals w0.2: J100.15@5.07,8.65 6.389,8.65 10.773,13.033 12.534,13.033 J108.2@14.501,15
NetJ100_16: J100.16@2.53,8.65 J107.2@28.732,15 | length 29.8
  Top Layer LF-signals w0.2: J100.16@2.53,8.65 3.757,7.423 5.87,7.423 11.007,12.56 26.291,12.56 J107.2@28.732,15
NetJ100_17: J100.17@5.07,6.11 J105.2@14.501,10 | length 11.5
  Top Layer LF-signals w0.2: J100.17@5.07,6.11 6.239,6.11 6.774,5.575 10.076,5.575 J105.2@14.501,10
NetJ100_18: J100.18@2.53,6.11 J106.2@28.732,10 | length 28.8
  Top Layer LF-signals w0.2: J100.18@2.53,6.11 3.745,4.895 9.992,4.895 12.611,7.514 26.246,7.514 J106.2@28.732,10
NetJ122_2: J122.2 XC100.1 | length 3.1
  Top Layer LF-signals w0.2: XC100.1 44.593,10.13 45.017,9.706 J122.2
NetR108_2: R108.2 SW100.2 SW100.4 | length 5.7
  Top Layer LF-signals w0.2: SW100.4 54.592,3.3 54.611,3.318 R108.2
NetR115_2: R115.2 U103.3 | length 2.9
  Top Layer LF-signals w0.2: R115.2 33.999,3.276 33.999,4.121 34.156,4.277 U103.3
RTC_CLKN: C108.1 J122.1 U102.34 | length 3.7
  Top Layer LF-signals w0.2: J122.1 47.777,9.856 47.777,11.101 C108.1 47.895,11.241 48.411,11.758 U102.34
RTC_CLKP: J121.1 R116.2 R117.1 U102.33 | length 9.1
  Top Layer LF-signals w0.2: R117.1 43.925,13.98 45.36,13.98 R116.2 ; J121.1 47.116,12.368 U102.33 ; J121.1@46.419,13.265 R116.2@46.419,14.849
SPI_MISO: J105.1@11.961,10 J112.2 U102.25 | length 53.8
  Top Layer LF-signals w0.2: J112.2@37.981,7.862 38.621,7.862 38.758,8 40.212,8 40.901,8.689 40.901,10.984 40.631,11.254 v1(40.631,11.95) 40.606,11.976 40.606,16.298 43.423,19.115 46.929,19.115 48.8,17.245 U102.25
  Bottom Layer LF-signals w0.2: J105.1@11.961,10 11.961,8.615 12.65,7.925 32.431,7.925 36.055,11.549 38.982,11.549 39.383,11.95 v1(40.631,11.95)
SPI_MOSI: J107.1@26.192,15 J115.2 U102.23 | length 32.6
  Top Layer LF-signals w0.2: J115.2 37.694,18.727 37.855,18.888 39.484,18.888 ; 39.744,18.888 39.484,18.888 ; v1(39.752,17.311) 39.752,18.62 ; 39.752,19.191 39.752,19.156 ; U102.23 49.967,19.4 49.552,19.815 40.049,19.815 39.752,19.518 39.752,19.156 ; 39.484,18.888 39.752,19.156 ; 39.484,18.888 39.752,18.62 ; 39.752,18.62 39.752,19.156
  Bottom Layer LF-signals w0.2: J107.1@26.192,15 26.192,16.689 26.814,17.311 v1(39.752,17.311) 39.752,17.411 v1@39.68,17.34
SPI_SCK: J106.1@26.192,10 J117.2 U102.22 | length 38.2
  Top Layer LF-signals w0.2: v1(34.231,11.95) 34.231,12.654 33.631,13.254 33.631,17.282 32.972,17.941 32.972,18.741 33.586,19.355 34.37,19.355 ; J117.2 34.644,19.081 ; U102.22 50.577,19.665 50.076,20.165 38.075,20.165 37.265,19.355 34.918,19.355 ; 34.37,19.355 34.644,19.081 ; 34.37,19.355 34.661,19.355 ; 34.644,19.081 34.918,19.355 ; 34.644,19.081 34.644,19.338 34.661,19.355 ; 34.661,19.355 34.918,19.355
  Bottom Layer LF-signals w0.2: J106.1@26.192,10 26.192,11.154 26.637,11.6 33.881,11.6 v1(34.231,11.95)
SPI_SS: J108.1@11.961,15 J110.2 U102.24 | length 51.4
  Top Layer LF-signals w0.2: v1(33.031,13.5) 33.031,12.884 33.416,12.5 33.416,8.852 34.405,7.862 J110.2@34.869,7.862 ; v1(42.452,19.011) 42.906,19.465 47.074,19.465 48.685,17.854 U102.24
  Bottom Layer LF-signals w0.2: J108.1@11.961,15 11.961,13.324 12.552,12.733 32.264,12.733 v1(33.031,13.5) 34.94,15.409 42.041,15.409 42.452,15.82 v1(42.452,19.011)
SWDCLK: J119.4@25.962,3.635 U102.12 | length 46.5
  Top Layer LF-signals w0.2: v1@56.107,20.739 56.673,20.173 U102.12
  Mid-Layer 1 w0.2: v1(39.181,7.45) 38.712,7.919 38.712,12.153 39.431,12.872 39.431,15.991 40.452,17.011 v1(40.452,19.011)
  Bottom Layer LF-signals w0.2: J119.4@25.962,3.635 25.962,4.865 26.347,5.25 30.349,5.25 31.789,6.689 37.297,6.689 38.058,7.45 v1(39.181,7.45) ; v1@40.445,19.018 41.36,19.934 54.504,19.934 54.689,20.119 55.413,20.119 v1(56.063,20.769)
SWDIO: J119.2@24.692,3.635 U102.13 | length 47
  Top Layer LF-signals w0.2: U102.13 v1@56.063,19.631
  Mid-Layer 1 w0.2: v1(40.081,7.45) 39.062,8.469 39.062,11.888 39.781,12.607 39.781,15.846 41.452,17.516 v1(41.452,19.011)
  Bottom Layer LF-signals w0.2: J119.2@24.692,3.635 24.692,4.946 25.346,5.6 30.135,5.6 31.591,7.056 36.921,7.056 37.865,8 39.531,8 v1(40.081,7.45) ; v1@41.445,19.018 42.01,19.584 54.649,19.584 54.834,19.769 v1(56.063,19.769)
UART_CTS: J101.2@28.732,25 J107.3@31.272,15 J111.2 U102.20 | length 48.2
  Top Layer LF-signals w0.2: J101.2@28.732,25 31.136,22.596 31.136,21.599 32.535,20.2 36.975,20.2 37.663,20.888 50.545,20.888 51.796,19.637 U102.20 ; J107.3@31.272,15 31.272,13.603 33.066,11.809 33.066,8.26 34.409,6.917 J111.2@34.869,6.917
  Mid-Layer 1 w0.2: J101.2@28.732,25 28.732,23.151 31.272,20.611 J107.3@31.272,15
UART_RTS: J102.2@17.041,25 J106.3@31.272,10 J113.2 U102.21 | length 63.6
  Top Layer LF-signals w0.2: v1(29.981,22.75) 30.495,22.236 30.495,21.745 32.39,19.85 37.265,19.85 37.953,20.538 50.4,20.538 51.186,19.752 U102.21 ; J106.3@31.272,10 31.272,7.504 32.502,6.274 37.716,6.274 37.981,6.54 J113.2@37.981,6.916
  Mid-Layer 1 w0.2: v1(29.981,22.75) 31.69,21.041 31.69,16.274 33.617,14.347 33.617,12.345 J106.3@31.272,10
  Bottom Layer LF-signals w0.2: J102.2@17.041,25 20.359,25 22.609,22.75 v1(29.981,22.75)
UART_RXD: J103.2@17.041,20 J105.3@17.041,10 J116.2 U102.14 | length 58
  Top Layer LF-signals w0.2: v1(33.824,18.8) 33.824,17.783 J116.2 ; v1(54.844,21.769) 55.453,21.159 U102.14
  Mid-Layer 1 w0.2: J105.3@17.041,10 19.056,12.015 19.056,17.985 J103.2@17.041,20
  Bottom Layer LF-signals w0.2: J103.2@17.041,20 18.541,20 20.218,21.677 29.611,21.677 32.488,18.8 v1(33.824,18.8) 36.114,18.8 38.066,20.753 53.828,20.753 v1(54.844,21.769)
UART_TXD: J104.2@28.732,20 J108.3@17.041,15 J114.2 U102.15 | length 46.1
  Top Layer LF-signals w0.2: J108.3@17.041,15 19.188,17.148 25.879,17.148 J104.2@28.732,20 ; v1(36.637,18.24) 36.637,18.44 36.674,18.403 36.674,17.352 37.063,16.962 J114.2 ; U102.15 v1(54.844,20.769)
  Bottom Layer LF-signals w0.2: J104.2@28.732,20 30.793,20 32.543,18.25 36.447,18.25 v1@36.537,18.34 ; v1(36.637,18.24) 38.681,20.284 54.359,20.284 v1(54.844,20.769)
VBAT_P3V3: C105.1 R112.1 U102.27 | length 5
  Top Layer LF-signals w0.35: C105.1 47.471,16.45 47.911,16.01 49.444,16.01 U102.27
  Top Layer LF-signals w0.7: R112.1@46.078,17.999 46.229,17.847 C105.1
VCC_MODULE_P3V3: J109.2@19.114,3 R102.1 R109.2 R111.2 R112.2 R118.1 | length 68.1
  Top Layer LF-signals w0.5: v1(43.637,18.14) 44.519,18.14 R112.2 v1(44.529,17.355) ; v1(49.456,6.503) 50.342,6.503 R118.1 ; v1@49.974,4.85 v1(49.974,4.9) ; v1@50.124,4.9 R102.1 ; v1(52.528,5.74) R111.2 v1(53.311,6.59)
  Top Layer LF-signals w1: R109.2 18.568,4.7 19.114,4.154 J109.2@19.114,3
  Mid-Layer 1 w0.5: v1(49.974,4.9) 51.688,4.9 v1(52.528,5.74)
  Mid-Layer 1 w1: J109.2@19.114,3 19.114,4.472 20.304,5.662 29.923,5.662 30.712,6.451 40.74,6.451 ; 41.54,6.479 41.54,7.145 ; v1(44.529,17.355) 43.744,18.14 v1(43.637,18.14) 42.729,17.232 42.729,9.213 41.54,8.023 41.54,7.251 ; v1(53.311,6.59) 52.528,5.807 v1(52.528,5.74) 51.817,6.451 42.234,6.451 ; 40.74,6.451 42.234,6.451 ; 40.74,6.451 41.54,7.251 ; 41.54,7.145 42.234,6.451 ; 41.54,7.145 41.54,7.251
VCC_TARGET_P3V3: C101.1 C104.1 J100.20@2.53,3.57 J109.1@16.574,3 J119.1@24.692,2.365 R109.1 R113.1 R114.2 R115.1 U103.8 | length 57.7
  Top Layer LF-signals w0.2: J100.20@2.53,3.57 2.53,1.962 C101.1 ; R115.1 R113.1 ; C104.1@39.01,5.277 C104.1
  Top Layer LF-signals w0.3: v1(31.199,5.126) R114.2 ; v1(31.201,3.8) 31.216,3.784 R113.1 ; U103.8 C104.1@39.01,5.277 ; C104.1 v1(39.94,5.062)
  Top Layer LF-signals w1: R109.1 J109.1@16.574,3
  Bottom Layer LF-signals w0.3: J119.1@24.692,2.365 24.692,1.694 25.028,1.358 30.832,1.358 ; v1(31.199,5.126) 31.199,1.725 ; v1(39.94,5.062) 38.329,5.062 34.626,1.358 31.565,1.358 ; 30.832,1.358 31.199,1.725 ; 30.832,1.358 31.565,1.358 ; 31.199,1.725 31.565,1.358
  Bottom Layer LF-signals w0.5: J109.1@16.574,3 18.153,4.58 20.906,4.58 23.121,2.365 J119.1@24.692,2.365
  Bottom Layer LF-signals w1: J100.20@2.53,3.57 4.13,1.97 11.395,1.97 12.426,3 J109.1@16.574,3
VDDIO_P3V3: C107.1 R111.1 U102.7 | length 4.5
  Top Layer LF-signals w0.35: U102.7 54.062,11.234 C107.1@54.062,8.299
  Top Layer LF-signals w0.7: R111.1 54.053,8.29 C107.1@54.062,8.299
VDDIO_SW: C103.1 R110.2 U101.3 U101.7 U101.8 U102.10 | length 37.3
  Top Layer LF-signals w0.2: v1(55.885,9.673) U102.10
  Top Layer LF-signals w0.3: R110.2 35.234,11.984 ; U101.8 35.832,14.3 34.231,14.3 34.23,14.299 34.23,13.22 35.234,12.216 ; U101.7 37.102,12.707 ; U101.3 38.372,11.868 v1(37.823,12.417) 37.417,12.417 ; 35.234,11.984 35.234,12.216 ; 35.234,11.984 35.466,12.216 ; 35.234,12.216 35.466,12.216 ; 35.466,12.216 35.666,12.417 36.812,12.417 ; 36.812,12.417 37.102,12.707 ; 36.812,12.417 37.099,12.417 ; 37.099,12.417 37.102,12.419 37.102,12.707 ; 37.099,12.417 37.417,12.417 ; 37.102,12.707 37.127,12.707 37.417,12.417
  Bottom Layer LF-signals w0.3: v1(37.823,12.417) 39.41,12.417 39.628,12.634 41.437,12.634 41.844,13.041 45.477,13.041 48.711,9.806 50.103,9.806 51.169,8.74 54.952,8.74 v1(55.885,9.673)
WAKE: J100.3@5.07,23.89 R118.2 U102.1 | length 74.8
  Top Layer LF-signals w0.2: v1(49.212,8.614) 50.432,8.614 50.399,8.648 U102.1
  Bottom Layer LF-signals w0.2: J100.3@5.07,23.89 3.68,22.5 1.331,22.5 1.072,22.241 1.072,10.371 1.509,9.934 7.999,9.934 11.983,5.95 29.99,5.95 31.615,7.575 32.576,7.575 35.851,10.85 40.309,10.85 42.1,12.641 45.186,12.641 v1(49.212,8.614)
pads on no net: J100.1@5.07,26.43 J100.2@2.53,26.43 J100.3@5.07,23.89 J100.4@2.53,23.89 J100.5@5.07,21.35 J100.6@2.53,21.35 J100.7@5.07,18.81 J100.8@2.53,18.81 J100.9@5.07,16.27 J100.10@2.53,16.27 J100.11@5.07,13.73 J100.12@2.53,13.73 J100.13@5.07,11.19 J100.14@2.53,11.19 J100.15@5.07,8.65 J100.16@2.53,8.65 J100.17@5.07,6.11 J100.18@2.53,6.11 J100.19@5.07,3.57 J100.20@2.53,3.57 J101.1@26.192,25 J101.2@28.732,25 J102.1@14.501,25 J102.2@17.041,25 J103.1@14.501,20 J103.2@17.041,20 J104.1@26.192,20 J104.2@28.732,20 J105.1@11.961,10 J105.2@14.501,10 J105.3@17.041,10 J106.1@26.192,10 J106.2@28.732,10 J106.3@31.272,10 J107.1@26.192,15 J107.2@28.732,15 J107.3@31.272,15 J108.1@11.961,15 J108.2@14.501,15 J108.3@17.041,15 J109.1@16.574,3 J109.2@19.114,3 J118.1@36.032,21.695 J118.2@36.032,24.235 J118.3@36.032,26.775 J119.1@24.692,2.365 J119.2@24.692,3.635 J119.3@25.962,2.365 J119.4@25.962,3.635 J119.5@27.232,2.365 J119.6 J119.7 J119.8 J119.9@29.772,2.365 J119.10@29.772,3.635 J120.0 J120.1@43.362,24.25 J120.2@43.362,26.79 J120.3@45.902,26.79 J120.4 U100.1 U100.2 U100.3 U100.6 U100.7 U103.0

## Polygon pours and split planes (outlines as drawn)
GND on Top Layer LF-signals "GND" (solid, remove dead copper, pour order 4): 3.624,0.395 3.629,0.4 56.343,0.4 56.8,0.857 56.8,29.2 56.4,29.6 0.8,29.6 0.4,29.2 0.4,0.659 0.659,0.4
GND on Bottom Layer LF-signals "GND" (solid, remove dead copper, pour order 5): 3.624,0.395 3.629,0.4 56.343,0.4 56.8,0.857 56.8,29.2 56.4,29.6 0.8,29.6 0.4,29.2 0.4,0.659 0.659,0.4
GND on Mid-Layer 1 "GND" (solid, remove dead copper, pour order 6): 3.624,0.395 3.629,0.4 56.343,0.4 56.8,0.857 56.8,29.2 56.4,29.6 0.8,29.6 0.4,29.2 0.4,0.659 0.659,0.4
GND on GND (split plane): 56.8,0.352 0.352,0.352 0.352,13.25 0.345,13.319 0.325,13.385 0.292,13.445 0.249,13.499 0.195,13.542 0.135,13.575 0.069,13.595 0,13.602 -6.148,13.602 -6.148,16.398 0,16.398 0.069,16.405 0.135,16.425 0.195,16.458 0.249,16.501 0.292,16.555 0.325,16.615 0.345,16.681 0.352,16.75 0.352,29.648 56.8,29.648

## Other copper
Top Layer LF-signals:
  rectangle net GND: 51.059,12.575 55.521,17.003
  pour cut-out: 15.131,5.775 15.131,7.225 18.331,7.225 18.331,5.775
  pour cut-out: 50.058,18.008 50.058,19.528 58.339,19.528 58.339,18.008
  pour cut-out: 49.881,10.479 49.881,12 58.161,12 58.161,10.479
  pour cut-out: 20.384,1.52 15.304,1.52 15.304,4.48 20.384,4.48
  pour cut-out: 30.732,1 23.732,1 23.732,5 30.732,5
  pour cut-out: 14.199,2.25 12.749,2.25 12.749,5.45 14.199,5.45
  pour cut-out: 4.999,0.743 2.499,0.743 2.499,1.843 4.999,1.843
  pour cut-out: 33.8,1.852 31.305,1.852 31.305,5.701 33.805,5.701
  pour cut-out: 34.052,3.227 39.776,3.227 39.776,5.827 34.052,5.827
  pour cut-out: 49.931,3.86 49.931,1.011 55.282,1.011 55.282,3.84
  pour cut-out: 55.261,3.727 55.261,5.475 50.074,5.475 50.074,3.743
  pour cut-out: 49.707,6.164 54.533,6.164 54.533,9.364 49.707,9.364
  pour cut-out: 49.881,8.981 45.128,8.981 45.128,12.53 49.881,12.53
  pour cut-out: 45.293,3.173 45.293,12.383 39.531,12.383 39.531,3.173
  pour cut-out: 43.979,12.53 43.979,18.875 47.179,18.875 47.179,12.53
  pour cut-out: 44.329,12.386 44.329,15.574 39.958,15.574 39.958,12.386
  pour cut-out: 40.971,5.802 33.655,5.802 33.655,19.355 40.971,19.355 40.971,16.152
  pour cut-out: 50.22,11.24 48.699,11.24 48.699,19.52 50.22,19.52
  pour cut-out: 10.821,14.725 10.821,20.975 7.621,20.975 7.621,14.725
  pour cut-out: 9.64,20.597 13.316,20.597 13.316,27.105 7.27,27.105 7.27,24.255 9.64,24.255
  pour cut-out: 0.915,2.366 6.296,2.366 6.296,28.115 -0.042,28.115 -0.042,2.366 0.123,2.366
  pour cut-out: 18.311,8.52 10.691,8.52 10.691,13.736 18.311,13.736
  pour cut-out: 32.988,8.52 24.922,8.52 24.922,11.48 32.988,11.48
  pour cut-out: 32.542,13.52 24.922,13.52 24.922,16.48 32.542,16.48
  pour cut-out: 18.311,13.52 10.691,13.52 10.691,16.48 18.311,16.48
  pour cut-out: 18.311,18.52 13.231,18.52 13.231,21.48 18.311,21.48
  pour cut-out: 30.002,18.52 24.922,18.52 24.922,21.48 30.002,21.48
  pour cut-out: 30.002,23.52 24.922,23.52 24.922,26.48 30.002,26.48
  pour cut-out: 18.311,17.784 13.231,17.784 13.231,21.48 18.311,21.48
  pour cut-out: 18.311,23.52 13.231,23.52 13.231,26.48 18.311,26.48
  pour cut-out: 34.447,20.477 37.407,20.477 37.407,28.097 34.447,28.097
  pour cut-out: 41.932,22.94 47.332,22.94 47.332,28.12 41.932,28.12
Bottom Layer LF-signals:
  pour cut-out: 30.832,1.358 30.832,4.499 23.914,4.499 23.914,1.358
  pour cut-out: 0.915,2.366 6.296,2.366 6.296,28.115 -0.042,28.115 -0.042,2.366 0.123,2.366
  pour cut-out: 41.805,14.267 41.805,12.684 43.351,12.684 43.351,14.42
GND (plane layer: these items are gaps in the copper):
  rectangle: 56.8,0 60,30

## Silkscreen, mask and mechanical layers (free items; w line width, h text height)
Top Overlay:
  text "MS4" at 49.923,25.392 h1.52 r90
  text "MS3" at 51.533,25.392 h1.52 r90
  text "MS2" at 52.927,25.392 h1.52 r90
  text "GPIO5" at 54.382,25.392 h1.52 r90
  text "GPIO4" at 55.911,25.392 h1.52 r90
  text "I2C" at 41.218,24.348 h1.52 r90
  text "UART" at 33.425,22.898 h1.52 r90
  text "23" at 50,19.6 h1.52 r90
  text "12" at 56.8,19.6 h1.52 r90
  text "24" at 47.284,17.417 h1.52
  text "1" at 50,9.6 h1.52
  text "11" at 55.313,9.6 h1.52
  text "SWD" at 25.882,5.644 h1.52
  text "CHIP" at 46.661,2.777 h1.3
  text "EN" at 46.811,1.677 h1.3
  text "CURR" at 22.002,1.017 h1.52 r90
Bottom Overlay:
  lines w0.25: 11.961,8.7 11.961,7.2 17.125,7.2 ; 11.961,11.3 11.961,13.7 ; 17.041,11.3 17.041,13.7 ; 17.041,16.3 17.041,17.8 21.931,17.8 ; 21.027,7.2 26.192,7.2 26.192,8.7 ; 26.192,11.3 26.192,13.7 ; 26.643,17.8 31.272,17.8 31.272,16.3 ; 31.272,11.3 31.272,13.7
  text "Atmel Corp © 2016" at 22.772,27.167 h2
  text "b" at 49.652,19.738 h6.5
  text "UART" at 26.06,17.324 h1.52
  text "PRO" at 36.544,17.044 h1
  text "PLAINED" at 43.596,17.032 h1.5
  text "X" at 46.121,17.032 h2.5
  text "BTLC1000ZR" at 55.8,17.05 h1.5
  text "p" at 6.53,16.665 h6.5 r270
  text "t" at 7.554,13.035 h5 r270
  text "A08-2579 Rev 2" at 51.785,10.069 h2
  text "c" at 7.438,8.694 h4 r270
  text "SPI" at 20.249,6.702 h1.52
  text "GPIO18" at 44.154,2.99 h1.52 r270
  text "GPIO2" at 39.097,2.955 h1.52 r270
  text "GPIO17" at 41.629,2.969 h1.52 r270
Mechanical 1:
  the board outline again, w0.2

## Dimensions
0,0 to 60,0 on Mechanical 4
-6.5,13.25 to 0,0 on Mechanical 4
-6.5,13.25 to 60,0 on Mechanical 4
0,0 to 0,30 on Mechanical 4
